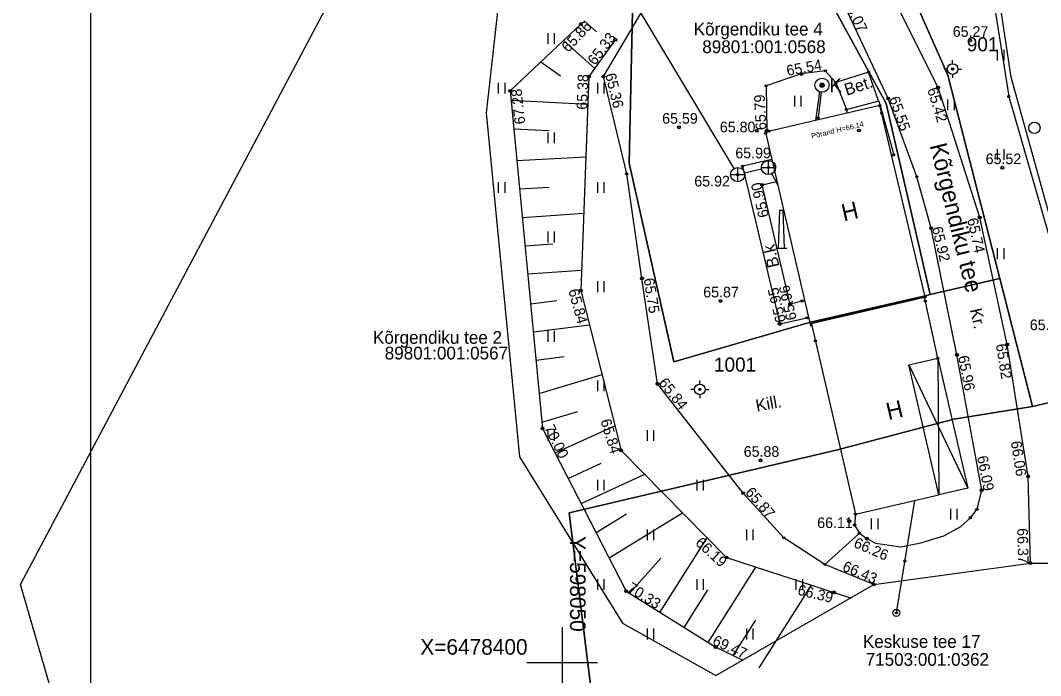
# Model space of a CAD drawing. Extents: x 598011 to 598230, y 6478330 to 6478537.
# Drawn here: x 598011.8 to 598083.7, y 6478399.1 to 6478445.3 of the extents above; entities that cross this region are included whole.
import ezdxf

# ---------------------------------------------------------------- set-up
doc = ezdxf.new("R2010")
doc.units = 0
for name, color, linetype in [('ALUSVORK', 7, 'Continuous'), ('HALJASTUS', 7, 'Continuous'), ('KKAEV', 7, 'Continuous'), ('KORGUS-EH2000', 7, 'Continuous'), ('KTRASS', 7, 'Continuous'), ('L_AADRESS', 7, 'Continuous'), ('MOOTMPUNKT', 7, 'Continuous'), ('MOOTPIIR', 7, 'Continuous'), ('MPKAABEL', 7, 'Continuous'), ('MPOHULIIN', 7, 'Continuous'), ('PIIR', 7, 'Continuous'), ('POST', 7, 'Continuous'), ('RELJEEF', 7, 'Continuous'), ('TEE', 7, 'Continuous'), ('TUNNUS', 7, 'Continuous'), ('VKAEV', 7, 'Continuous'), ('VORK', 7, 'Continuous'), ('VORMISTUS', 7, 'Continuous'), ('VTRASS', 7, 'Continuous')]:
    doc.layers.add(name, color=color, linetype=linetype)

msp = doc.modelspace()

# ---------------------------------------------------------------- linework, layer by layer
at = {"layer": 'ALUSVORK'}
for p, q in [((598077.533, 6478442.228), (598077.533, 6478442.478)), ((598077.158, 6478441.853), (598076.908, 6478441.853)), ((598077.908, 6478441.853), (598078.158, 6478441.853)), ((598077.533, 6478441.478), (598077.533, 6478441.228)), ((598059.704, 6478419.634), (598059.704, 6478419.884)), ((598059.329, 6478419.259), (598059.079, 6478419.259)), ((598059.704, 6478418.884), (598059.704, 6478418.634)), ((598060.079, 6478419.259), (598060.329, 6478419.259))]:
    msp.add_line(p, q, dxfattribs=at)
for centre, radius in [((598077.533, 6478441.853), 0.375), ((598077.533, 6478441.853), 0.022), ((598059.704, 6478419.259), 0.375), ((598059.704, 6478419.259), 0.022)]:
    msp.add_circle(centre, radius, dxfattribs=at)
at = {"layer": 'HALJASTUS'}
for p, q in [((598048.987, 6478444.385), (598048.987, 6478443.624)), ((598049.442, 6478444.385), (598049.442, 6478443.624)), ((598080.681, 6478443.214), (598080.681, 6478442.453)), ((598081.136, 6478443.214), (598081.136, 6478442.453)), ((598045.487, 6478440.885), (598045.487, 6478440.124)), ((598045.942, 6478440.885), (598045.942, 6478440.124)), ((598052.487, 6478440.885), (598052.487, 6478440.124)), ((598052.942, 6478440.885), (598052.942, 6478440.124)), ((598066.381, 6478439.968), (598066.381, 6478439.207)), ((598066.836, 6478439.968), (598066.836, 6478439.207)), ((598077.181, 6478439.714), (598077.181, 6478438.953)), ((598077.636, 6478439.714), (598077.636, 6478438.953)), ((598048.987, 6478437.385), (598048.987, 6478436.624)), ((598049.442, 6478437.385), (598049.442, 6478436.624)), ((598080.681, 6478436.214), (598080.681, 6478435.453)), ((598081.136, 6478436.214), (598081.136, 6478435.453)), ((598045.487, 6478433.885), (598045.487, 6478433.124)), ((598045.942, 6478433.885), (598045.942, 6478433.124)), ((598052.487, 6478433.885), (598052.487, 6478433.124)), ((598052.942, 6478433.885), (598052.942, 6478433.124)), ((598048.987, 6478430.385), (598048.987, 6478429.624)), ((598049.442, 6478430.385), (598049.442, 6478429.624)), ((598080.681, 6478429.214), (598080.681, 6478428.453)), ((598081.136, 6478429.214), (598081.136, 6478428.453)), ((598052.487, 6478426.885), (598052.487, 6478426.124)), ((598052.942, 6478426.885), (598052.942, 6478426.124)), ((598048.987, 6478423.385), (598048.987, 6478422.624)), ((598049.442, 6478423.385), (598049.442, 6478422.624)), ((598052.487, 6478419.885), (598052.487, 6478419.124)), ((598052.942, 6478419.885), (598052.942, 6478419.124)), ((598048.987, 6478416.385), (598048.987, 6478415.624)), ((598049.442, 6478416.385), (598049.442, 6478415.624)), ((598055.987, 6478416.385), (598055.987, 6478415.624)), ((598056.442, 6478416.385), (598056.442, 6478415.624)), ((598052.487, 6478412.885), (598052.487, 6478412.124)), ((598052.942, 6478412.885), (598052.942, 6478412.124)), ((598059.487, 6478412.885), (598059.487, 6478412.124)), ((598059.942, 6478412.885), (598059.942, 6478412.124)), ((598077.385, 6478410.846), (598077.385, 6478410.085)), ((598077.84, 6478410.846), (598077.84, 6478410.085)), ((598071.8, 6478410.156), (598071.8, 6478409.395)), ((598072.255, 6478410.156), (598072.255, 6478409.395)), ((598055.987, 6478409.385), (598055.987, 6478408.624)), ((598056.442, 6478409.385), (598056.442, 6478408.624)), ((598062.987, 6478409.385), (598062.987, 6478408.624)), ((598063.442, 6478409.385), (598063.442, 6478408.624)), ((598052.487, 6478405.885), (598052.487, 6478405.124)), ((598052.942, 6478405.885), (598052.942, 6478405.124)), ((598059.487, 6478405.885), (598059.487, 6478405.124)), ((598059.942, 6478405.885), (598059.942, 6478405.124)), ((598066.487, 6478405.885), (598066.487, 6478405.124)), ((598066.942, 6478405.885), (598066.942, 6478405.124)), ((598055.987, 6478402.385), (598055.987, 6478401.624)), ((598056.442, 6478402.385), (598056.442, 6478401.624)), ((598062.987, 6478402.385), (598062.987, 6478401.624)), ((598063.442, 6478402.385), (598063.442, 6478401.624))]:
    msp.add_line(p, q, dxfattribs=at)
msp.add_lwpolyline([(598074.027, 6478475.285), (598073.77, 6478466.095), (598078.481, 6478457.792), (598076.946, 6478452.332), (598080.553, 6478445.829), (598081.491, 6478439.919), (598087.787, 6478418.044), (598088.752, 6478412.268)], dxfattribs=at)
msp.add_circle((598083.3, 6478437.706), 0.4, dxfattribs=at)
at = {"layer": 'KKAEV'}
for p, q in [((598064.55, 6478434.407), (598064.55, 6478435.407)), ((598061.877, 6478434.408), (598062.877, 6478434.408)), ((598062.377, 6478433.908), (598062.377, 6478434.908)), ((598064.05, 6478434.907), (598065.05, 6478434.907))]:
    msp.add_line(p, q, dxfattribs=at)
for centre in [(598064.55, 6478434.907), (598062.377, 6478434.408)]:
    msp.add_circle(centre, 0.5, dxfattribs=at)
at = {"layer": 'KORGUS-EH2000'}
for centre in [(598051.31, 6478445.027), (598053.745, 6478443.926), (598078.763, 6478443.876), (598066.861, 6478441.508), (598051.884, 6478441.321), (598052.912, 6478441.326), (598046.338, 6478440.312), (598076.505, 6478440.548), (598072.988, 6478439.778), (598058.233, 6478437.749), (598063.723, 6478437.507), (598064.421, 6478437.504), (598070.926, 6478437.514), (598081.045, 6478434.897), (598064.107, 6478433.679), (598079.441, 6478431.381), (598076.015, 6478430.626), (598055.627, 6478427.092), (598051.307, 6478426.24), (598061.165, 6478425.497), (598066.065, 6478425.278), (598065.34, 6478423.875), (598081.386, 6478422.423), (598077.84, 6478421.699), (598056.731, 6478419.641), (598048.614, 6478416.513), (598054.161, 6478414.961), (598063.984, 6478414.255), (598082.86, 6478413.124), (598079.586, 6478412.147), (598062.762, 6478411.945), (598070.246, 6478409.976), (598071.48, 6478408.732), (598061.588, 6478407.401), (598083.023, 6478407.009), (598071.972, 6478405.5), (598054.506, 6478405.025), (598069.167, 6478404.941), (598060.824, 6478401.082)]:
    msp.add_circle(centre, 0.1, dxfattribs=at)
at = {"layer": 'KTRASS'}
for points in [[(598062.121, 6478434.837), (598054.532, 6478447.542)], [(598064.063, 6478434.794), (598062.864, 6478434.52)], [(598064.779, 6478434.462), (598065.188, 6478433.717)]]:
    msp.add_lwpolyline(points, dxfattribs=at)
at = {"layer": 'L_AADRESS'}
for p, q in [((598065.36, 6478431.9), (598065.553, 6478431.9)), ((598065.553, 6478431.9), (598065.649, 6478429.205)), ((598065.842, 6478429.205), (598065.072, 6478429.205)), ((598065.649, 6478429.205), (598065.264, 6478429.205))]:
    msp.add_line(p, q, dxfattribs=at)
msp.add_lwpolyline([(598065.554, 6478431.9), (598065.649, 6478429.205), (598065.264, 6478429.205), (598065.359, 6478431.9)], close=True, dxfattribs=at)
at = {"layer": 'MOOTMPUNKT'}
for centre in [(598051.31, 6478445.027), (598053.745, 6478443.926), (598078.763, 6478443.876), (598066.861, 6478441.508), (598068.553, 6478441.728), (598071.609, 6478441.634), (598077.533, 6478441.853), (598051.884, 6478441.321), (598052.912, 6478441.326), (598069.297, 6478440.895), (598046.338, 6478440.312), (598064.377, 6478440.666), (598068.326, 6478440.711), (598068.327, 6478440.714), (598076.505, 6478440.548), (598072.988, 6478439.778), (598081.491, 6478439.919), (598070.043, 6478439.002), (598072.395, 6478439.274), (598072.525, 6478438.741), (598068.052, 6478438.414), (598058.233, 6478437.749), (598063.723, 6478437.507), (598064.348, 6478437.313), (598064.421, 6478437.504), (598064.6, 6478437.468), (598070.926, 6478437.514), (598073.267, 6478435.782), (598073.387, 6478435.8), (598054.548, 6478434.457), (598062.377, 6478434.408), (598062.711, 6478434.996), (598064.55, 6478434.907), (598064.979, 6478435.008), (598081.045, 6478434.897), (598064.107, 6478433.679), (598075.01, 6478434.257), (598079.441, 6478431.381), (598076.015, 6478430.626), (598055.627, 6478427.092), (598051.307, 6478426.24), (598075.602, 6478425.781), (598061.165, 6478425.497), (598066.065, 6478425.278), (598066.916, 6478425.493), (598075.607, 6478425.485), (598067.263, 6478424.306), (598065.34, 6478423.875), (598067.851, 6478422.688), (598081.386, 6478422.423), (598076.479, 6478421.454), (598077.84, 6478421.699), (598056.731, 6478419.641), (598059.704, 6478419.259), (598048.614, 6478416.513), (598054.161, 6478414.961), (598063.984, 6478414.255), (598082.86, 6478413.124), (598079.586, 6478412.147), (598062.762, 6478411.945), (598079.255, 6478410.806), (598070.246, 6478409.976), (598070.678, 6478410.454), (598078.785, 6478410.211), (598070.622, 6478409.694), (598070.958, 6478409.123), (598065.625, 6478408.796), (598071.48, 6478408.732), (598061.588, 6478407.401), (598074.163, 6478407.155), (598083.023, 6478407.009), (598068.524, 6478406.906), (598054.506, 6478405.025), (598069.167, 6478404.941), (598071.972, 6478405.5), (598073.566, 6478403.497), (598073.566, 6478403.497), (598060.824, 6478401.082)]:
    msp.add_circle(centre, 0.075, dxfattribs=at)
at = {"layer": 'MOOTPIIR'}
msp.add_lwpolyline([(598075.982, 6478475.56), (598057.177, 6478472.92), (598048.24, 6478469.789), (598045.814, 6478449.279), (598044.645, 6478438.772), (598046.991, 6478414.508), (598054.253, 6478402.767), (598060.844, 6478399.077), (598071.972, 6478405.5), (598083.023, 6478407.009), (598085.912, 6478407.009), (598087.125, 6478415.828), (598086.295, 6478424.582), (598081.666, 6478441.29), (598079.041, 6478458.618)], close=True, dxfattribs=at)
at = {"layer": 'MPKAABEL'}
msp.add_lwpolyline([(598067.893, 6478438.231), (598068.172, 6478440.239)], dxfattribs=at)
at = {"layer": 'MPOHULIIN'}
msp.add_lwpolyline([(598073.566, 6478403.497), (598074.86, 6478411.423)], dxfattribs=at)
at = {"layer": 'PIIR'}
for points in [[(598011.79, 6478405.5), (598081.48, 6478537.03), (598087.81, 6478533.61), (598081.1, 6478522.41), (598073.68, 6478503.38), (598068.04, 6478490.52), (598063.74, 6478475.61), (598063.42, 6478466.37), (598055.37, 6478465.26), (598054.72, 6478435.22), (598057.87, 6478421.2), (598067.5, 6478424), (598075.6, 6478425.87), (598075.95, 6478425.95), (598080.86, 6478427.08), (598083.16, 6478418.05), (598077.61, 6478417.15), (598069.31, 6478414.97), (598050.5, 6478410.56), (598053.52, 6478386.1), (598055.7, 6478377.93), (598019.25, 6478379.83)], [(598081.1, 6478522.41), (598087.81, 6478533.61), (598092.94, 6478530.49), (598086.45, 6478519.6), (598079.22, 6478501.09), (598073.69, 6478488.47), (598069.71, 6478474.66), (598069.29, 6478462.69), (598071.55, 6478454.2), (598077.2, 6478441.43), (598080.86, 6478427.08), (598075.95, 6478425.95), (598072.84, 6478439.42), (598065.87, 6478452.21), (598063.26, 6478462.01), (598063.42, 6478466.37), (598063.74, 6478475.61), (598068.04, 6478490.52), (598073.68, 6478503.38)], [(598093.38, 6478381.19), (598086.49, 6478418.82), (598083.16, 6478418.05), (598080.86, 6478427.08), (598077.2, 6478441.43), (598071.55, 6478454.2), (598069.29, 6478462.69), (598069.71, 6478474.66), (598073.69, 6478488.47), (598079.22, 6478501.09), (598086.45, 6478519.6), (598092.94, 6478530.49), (598127.2, 6478509.56), (598154.27, 6478492.13), (598192.62, 6478466.21), (598223.81, 6478441.55), (598229.65, 6478435.94), (598191.25, 6478412.44), (598173.37, 6478396.18), (598161.58, 6478385.58), (598151.68, 6478381.11), (598144.54, 6478375.38)], [(598054.72, 6478435.22), (598055.37, 6478465.26), (598063.42, 6478466.37), (598063.26, 6478462.01), (598065.87, 6478452.21), (598072.84, 6478439.42), (598075.95, 6478425.95), (598075.6, 6478425.87), (598067.5, 6478424), (598057.87, 6478421.2)], [(598130.96, 6478330.09), (598110.14, 6478369.56), (598053.52, 6478386.1), (598050.5, 6478410.56), (598069.31, 6478414.97), (598077.61, 6478417.15), (598083.16, 6478418.05), (598086.49, 6478418.82), (598093.38, 6478381.19), (598154.28, 6478374.27), (598158.87, 6478339.87), (598159.68, 6478333.85)]]:
    msp.add_lwpolyline(points, close=True, dxfattribs=at)
msp.add_lwpolyline([(598070.122, 6478438.747), (598070.043, 6478439.002), (598072.334, 6478439.614), (598073.387, 6478435.8), (598073.229, 6478435.776)], dxfattribs=at)
at = {"layer": 'POST'}
for radius in [0.25, 0.0234]:
    msp.add_circle((598073.566, 6478403.497), radius, dxfattribs=at)
at = {"layer": 'RELJEEF'}
for p, q in [((598051.542, 6478445.247), (598052.408, 6478444.471)), ((598050.086, 6478443.866), (598052.29, 6478441.89)), ((598048.502, 6478442.365), (598049.876, 6478441.381)), ((598046.4, 6478439.659), (598051.81, 6478439.374)), ((598046.593, 6478437.646), (598049.084, 6478437.515)), ((598046.807, 6478435.403), (598051.667, 6478435.659)), ((598046.998, 6478433.411), (598049.09, 6478433.521)), ((598047.192, 6478431.387), (598051.515, 6478431.681)), ((598047.382, 6478429.396), (598049.331, 6478429.528)), ((598047.572, 6478427.404), (598051.361, 6478427.661)), ((598047.774, 6478425.301), (598049.63, 6478425.54)), ((598047.964, 6478423.309), (598051.92, 6478423.818)), ((598048.155, 6478421.317), (598050.141, 6478421.573)), ((598048.379, 6478418.968), (598052.809, 6478420.305)), ((598048.573, 6478416.938), (598051.112, 6478417.704)), ((598049.503, 6478414.781), (598053.723, 6478416.693)), ((598050.423, 6478412.986), (598052.741, 6478414.052)), ((598051.336, 6478411.205), (598055.824, 6478413.269)), ((598052.385, 6478409.161), (598054.526, 6478410.479)), ((598053.3, 6478407.376), (598058.48, 6478410.564)), ((598056.893, 6478403.535), (598060.229, 6478408.784)), ((598054.747, 6478404.874), (598056.965, 6478407.359)), ((598060.287, 6478401.417), (598063.662, 6478406.728)), ((598058.59, 6478402.476), (598060.269, 6478405.118)), ((598063.888, 6478399.626), (598067.591, 6478405.453)), ((598062.068, 6478400.491), (598063.645, 6478402.972))]:
    msp.add_line(p, q, dxfattribs=at)
for points in [[(598051.31, 6478445.027), (598046.338, 6478440.312), (598048.614, 6478416.513), (598054.506, 6478405.025), (598060.824, 6478401.082), (598062.74, 6478400.172)], [(598053.745, 6478443.926), (598051.884, 6478441.321), (598051.307, 6478426.24), (598054.161, 6478414.961), (598061.588, 6478407.401), (598070.342, 6478404.559)]]:
    msp.add_lwpolyline(points, dxfattribs=at)
at = {"layer": 'TEE'}
for points in [[(598083.023, 6478407.009), (598082.86, 6478413.124), (598081.386, 6478422.423), (598079.441, 6478431.381), (598076.505, 6478440.548), (598072.945, 6478447.7), (598070.89, 6478452.828), (598069.283, 6478458.458), (598068.438, 6478463.424), (598068.218, 6478467.462), (598068.789, 6478474.55)], [(598070.678, 6478410.454), (598070.622, 6478409.694), (598070.958, 6478409.123), (598071.48, 6478408.732), (598072.088, 6478408.424), (598073.872, 6478408.153), (598075.289, 6478408.445), (598076.915, 6478408.925), (598078.103, 6478409.593), (598078.785, 6478410.211), (598079.255, 6478410.806), (598079.586, 6478412.147), (598077.84, 6478421.699), (598076.015, 6478430.626), (598075.01, 6478434.257), (598072.988, 6478439.778), (598069.764, 6478446.643), (598066.794, 6478453.152), (598065.186, 6478458.512), (598064.231, 6478463.307), (598063.905, 6478467.586), (598064.457, 6478473.942)], [(598071.972, 6478405.5), (598068.524, 6478406.906), (598065.625, 6478408.796), (598062.762, 6478411.945), (598056.731, 6478419.641), (598055.627, 6478427.092), (598054.548, 6478434.457), (598052.912, 6478441.326), (598056.847, 6478447.971), (598057.909, 6478453.658), (598055.952, 6478458.236), (598057.052, 6478463.147), (598060.567, 6478466.685), (598064.178, 6478470.73)], [(598069.297, 6478440.895), (598068.553, 6478441.728), (598066.861, 6478441.508), (598064.377, 6478440.666), (598064.422, 6478437.427)], [(598072.298, 6478439.604), (598071.609, 6478441.634), (598069.297, 6478440.895), (598070.043, 6478439.002)], [(598064.778, 6478435.47), (598062.711, 6478434.996), (598065.34, 6478423.875), (598067.38, 6478424.332)], [(598067.098, 6478425.539), (598066.065, 6478425.278), (598064.107, 6478433.679), (598065.141, 6478433.916)], [(598070.958, 6478409.123), (598068.524, 6478406.906)]]:
    msp.add_lwpolyline(points, dxfattribs=at)
at = {"layer": 'TUNNUS'}
for points in [[(598075.546, 6478425.768), (598075.602, 6478425.781), (598072.398, 6478439.275), (598064.327, 6478437.405), (598067.517, 6478423.744), (598067.602, 6478423.764), (598067.566, 6478423.919), (598075.546, 6478425.768)], [(598067.602, 6478423.764), (598070.678, 6478410.454), (598076.561, 6478411.817), (598074.443, 6478420.982), (598076.479, 6478421.454), (598075.546, 6478425.768), (598067.566, 6478423.919), (598067.602, 6478423.764)], [(598067.517, 6478423.744), (598067.602, 6478423.764)], [(598076.479, 6478421.454), (598078.597, 6478412.289), (598076.561, 6478411.817)], [(598076.479, 6478421.454), (598076.561, 6478411.817)], [(598074.443, 6478420.982), (598078.597, 6478412.289)]]:
    msp.add_lwpolyline(points, dxfattribs=at)
at = {"layer": 'VKAEV'}
for radius in [0.5, 0.15, 0.125, 0.1, 0.075, 0.05, 0.025]:
    msp.add_circle((598068.327, 6478440.714), radius, dxfattribs=at)
at = {"layer": 'VORK'}
for p, q in [((598050, 6478402.5), (598050, 6478397.5)), ((598047.5, 6478400), (598052.5, 6478400))]:
    msp.add_line(p, q, dxfattribs=at)
at = {"layer": 'VORMISTUS'}
msp.add_lwpolyline([(598109.249, 6478361.639), (598016.749, 6478361.639), (598016.749, 6478504.139), (598109.249, 6478504.139), (598109.249, 6478361.639)], dxfattribs=at)
at = {"layer": 'VTRASS'}
msp.add_lwpolyline([(598068.267, 6478440.218), (598068.034, 6478438.264)], dxfattribs=at)

# ---------------------------------------------------------------- texts
at = {"layer": 'ALUSVORK'}
for s, p in [('901', (598078.533, 6478443.103)), ('1001', (598060.704, 6478420.509))]:
    msp.add_text(s, height=1, dxfattribs=at).set_placement(p)
at = {"layer": 'KORGUS-EH2000'}
for s, rotation, p in [('65.07', 295.43055, (598069.805, 6478446.634)), ('65.86', 46.76736, (598050.423, 6478442.983)), ('65.33', 52.81046, (598052.316, 6478442.067)), ('65.54', 9.99181, (598065.888, 6478441.37)), ('65.38', 87.69656, (598051.757, 6478438.973)), ('65.36', 283.74227, (598053.027, 6478441.469)), ('67.28', 96.22923, (598047.4, 6478438.001)), ('65.42', 287.05162, (598075.732, 6478440.417)), ('65.79', 93.02613, (598064.404, 6478437.57)), ('65.55', 289.45639, (598073.035, 6478439.777)), ('65.90', 102.94051, (598064.591, 6478431.47)), ('65.74', 282.60507, (598078.553, 6478431.267)), ('65.92', 283.46492, (598076.067, 6478430.649)), ('65.75', 279.18803, (598055.739, 6478427.056)), ('65.96', 102.85636, (598066.551, 6478424.228)), ('65.84', 285.24277, (598050.427, 6478426.24)), ('65.95', 103.55934, (598065.796, 6478424.069)), ('65.82', 279.1996, (598080.578, 6478422.419)), ('65.96', 281.10384, (598077.911, 6478421.577)), ('65.84', 308.62536, (598056.763, 6478419.708)), ('65.84', 287.44263, (598052.685, 6478417.043)), ('70.00', 295.86008, (598048.722, 6478416.559)), ('66.06', 278.88187, (598081.635, 6478415.568)), ('66.09', 281.02362, (598079.255, 6478414.507)), ('65.87', 311.39952, (598062.859, 6478411.964)), ('66.37', 271.346, (598082.088, 6478409.462)), ('66.19', 317.36408, (598059.336, 6478408.368)), ('66.26', 336.5656, (598070.498, 6478408.165)), ('66.43', 337.00284, (598069.701, 6478406.503)), ('70.33', 327.88025, (598054.522, 6478405.067)), ('66.39', 346.38833, (598066.558, 6478404.784)), ('69.47', 335.4217, (598060.536, 6478401.283))]:
    msp.add_text(s, height=0.75, rotation=rotation, dxfattribs=at).set_placement(p)
for s, p in [('65.27', (598077.544, 6478444.126)), ('65.59', (598057.049, 6478437.999)), ('65.80', (598061.117, 6478437.39)), ('65.99', (598062.208, 6478435.559)), ('65.52', (598079.862, 6478435.147)), ('65.92', (598059.317, 6478433.572)), ('65.87', (598059.946, 6478425.747)), ('65.79', (598082.976, 6478423.439)), ('65.88', (598062.8, 6478414.505)), ('66.11', (598067.984, 6478409.483))]:
    msp.add_text(s, height=0.75, dxfattribs=at).set_placement(p)
at = {"layer": 'PIIR'}
for s, p in [('Kõrgendiku tee 4', (598059.276, 6478444.225)), ('89801:001:0568', (598059.878, 6478442.978)), ('Kõrgendiku tee 2', (598036.658, 6478422.475)), ('89801:001:0567', (598037.484, 6478421.372)), ('Keskuse tee 17', (598071.203, 6478401.03)), ('71503:001:0362', (598071.401, 6478399.764))]:
    msp.add_text(s, height=0.9, dxfattribs=at).set_placement(p)
msp.add_text('Põrand H=66.14', height=0.375, rotation=13.4561, dxfattribs=at).set_placement((598067.615, 6478436.934))
at = {"layer": 'TEE'}
for s, height, rotation, p in [('Bet.', 0.85, 18.05999, (598070.058, 6478439.967)), ('Kõrgendiku tee', 1.2, 283.9119, (598075.912, 6478436.468)), ('B.k', 0.85, 103.18387, (598065.332, 6478427.95)), ('Kr.', 0.85, 282.83727, (598078.741, 6478424.879)), ('Kill.', 0.85, 10.24684, (598063.726, 6478417.689))]:
    msp.add_text(s, height=height, rotation=rotation, dxfattribs=at).set_placement(p)
at = {"layer": 'TUNNUS'}
for p in [(598069.854, 6478431.103), (598073.003, 6478417.096)]:
    msp.add_text('H', height=1.2, rotation=13.13255, dxfattribs=at).set_placement(p)
at = {"layer": 'VKAEV'}
msp.add_text('K', height=1, dxfattribs=at).set_placement((598068.843, 6478440.208))
at = {"layer": 'VORK'}
msp.add_text('Y=598050', height=1.1, rotation=270, dxfattribs=at).set_placement((598050.55, 6478408.917))
msp.add_text('X=6478400', height=1.1, dxfattribs=at).set_placement((598039.992, 6478400.55))

doc.saveas('drawing.dxf')
